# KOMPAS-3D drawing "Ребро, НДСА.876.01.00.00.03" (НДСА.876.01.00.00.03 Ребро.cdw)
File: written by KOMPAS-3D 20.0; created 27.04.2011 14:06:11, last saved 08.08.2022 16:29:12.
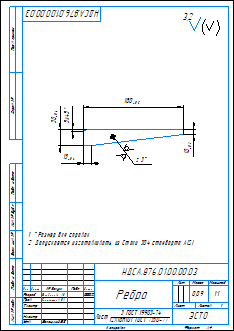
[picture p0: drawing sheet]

Sheet 1: A4, portrait

Document properties: Полное имя файла: C:\Users\cherbakova\Desktop\Барсук\НДСА.876.00.00.00.00 Нагреватель горизонтальный\НДСА.876.01.00.00.03 Ребро.cdw; Автор: Мочегов И.Н.; Организация: ЭСТО-Вакуум; Масса: 0.0885788; Знак неуказанной шероховатости: 4; Параметр неуказанной шероховатости: 3,2; 308917210546: <item xmlns="http://appius.ru/pdm" xmlns:xs="http://www.w3.org/2001/XMLSchema" xmlns:xsi="http://www.w3.org/2001/XMLSchema-instance" xsi:type="item">  <element xmlns:d2p1="http://v8.1c.ru/8.1/data/enterprise/current-config" xsi:type="d2p1:CatalogRef.aps_Элемен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; 308917210646: <item xmlns="http://appius.ru/pdm" xmlns:xs="http://www.w3.org/2001/XMLSchema" xmlns:xsi="http://www.w3.org/2001/XMLSchema-instance" xsi:type="item">  <element xmlns:d2p1="http://v8.1c.ru/8.1/data/enterprise/current-config" xsi:type="d2p1:CatalogRef.aps_Элемен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; 255457168322: <item xmlns="http://appius.ru/pdm" xmlns:xs="http://www.w3.org/2001/XMLSchema" xmlns:xsi="http://www.w3.org/2001/XMLSchema-instance" xsi:type="item">  <element xmlns:d2p1="http://v8.1c.ru/8.1/data/enterprise/current-config" xsi:type="d2p1:CatalogRef.aps_Элемен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; 255457168422: <item xmlns="http://appius.ru/pdm" xmlns:xs="http://www.w3.org/2001/XMLSchema" xmlns:xsi="http://www.w3.org/2001/XMLSchema-instance" xsi:type="item">  <element xmlns:d2p1="http://v8.1c.ru/8.1/data/enterprise/current-config" xsi:type="d2p1:CatalogRef.aps_Элемен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; 231528343800: <item xmlns="http://appius.ru/pdm" xmlns:xs="http://www.w3.org/2001/XMLSchema" xmlns:xsi="http://www.w3.org/2001/XMLSchema-instance" xsi:type="item">  <element xmlns:d2p1="http://v8.1c.ru/8.1/data/enterprise/current-config" xsi:type="d2p1:CatalogRef.aps_Элемен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; 231528343900: <item xmlns="http://appius.ru/pdm" xmlns:xs="http://www.w3.org/2001/XMLSchema" xmlns:xsi="http://www.w3.org/2001/XMLSchema-instance" xsi:type="item">  <element xmlns:d2p1="http://v8.1c.ru/8.1/data/enterprise/current-config" xsi:type="d2p1:CatalogRef.aps_Элемен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; 299858336019: <item xmlns="http://appius.ru/pdm" xmlns:xs="http://www.w3.org/2001/XMLSchema" xmlns:xsi="http://www.w3.org/2001/XMLSchema-instance" xsi:type="item">  <element xmlns:d2p1="http://v8.1c.ru/8.1/data/enterprise/current-config" xsi:type="d2p1:CatalogRef.aps_Элемен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; PLM_CDWXDTO: <item xmlns="http://appius.ru/pdm" xmlns:xs="http://www.w3.org/2001/XMLSchema" xmlns:xsi="http://www.w3.org/2001/XMLSchema-instance" xsi:type="item">  <element xmlns:d2p1="http://v8.1c.ru/8.1/data/enterprise/current-config" xsi:type="d2p1:CatalogRef.aps_Элемен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

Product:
- Part/product: Ребро  | designation НДСА.876.01.00.00.03
    Материал: Лист $b3 ГОСТ 19903-74;12Х18Н10Т ГОСТ 7350-77$ (density 7900 kg/m3)
    Масса: 0.0885788
    Раздел спецификации: Детали
    additional columns: <item xmlns="http://appius.ru/pdm" xmlns:xs="http://www.w3.org/2001/XMLSchema" x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; <item xmlns="http://appius.ru/pdm" xmlns:xs="http://www.w3.org/2001/XMLSchema" x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; <item xmlns="http://appius.ru/pdm" xmlns:xs="http://www.w3.org/2001/XMLSchema" x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; <item xmlns="http://appius.ru/pdm" xmlns:xs="http://www.w3.org/2001/XMLSchema" x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; <item xmlns="http://appius.ru/pdm" xmlns:xs="http://www.w3.org/2001/XMLSchema" x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; <item xmlns="http://appius.ru/pdm" xmlns:xs="http://www.w3.org/2001/XMLSchema" x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
    source file: НДСА.876.01.00.00.03 Ребро.cdw

Title block, sheet 1: Наименование: Ребро; designation: НДСА.876.01.00.00.03; Материал: Лист  3 ГОСТ 19903-74 12Х18Н10Т ГОСТ 7350-77; Масса: 0,09; scale: 1:1; Количество листов документа: 1; organisation: ЭСТО; Форматы листов документа: A4; stored path: C:\Documents and Settings\min\Мои документы\Мои файлы 1C-PDM\613023df-e845-423d-9d80-185697d4c68d\УКРД.772.08.02.00.03 Ребро.cdw; Разработал: Щербакова А.В.; Проверил: Горностаев П.А.; Утвердил: Белецкий В.Е.; Разработал, date: 03.08.2022

Views: Вид 1, Спереди
Referenced files in C:\Users\cherbakova\Desktop\PLM\: НДСА.876.01.00.00.03 Ребро.m3d
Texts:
  НДСА.876.01.00.00.03 Ребро
Dimensions and other numbers on the sheet: 15; 180; 5; 30; 10; 3,2; 1:1; 1; 0,09; 03.08.2022

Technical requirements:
  *Размер для справок
  Допускается изготавливать из Стали 304 стандарта AISI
